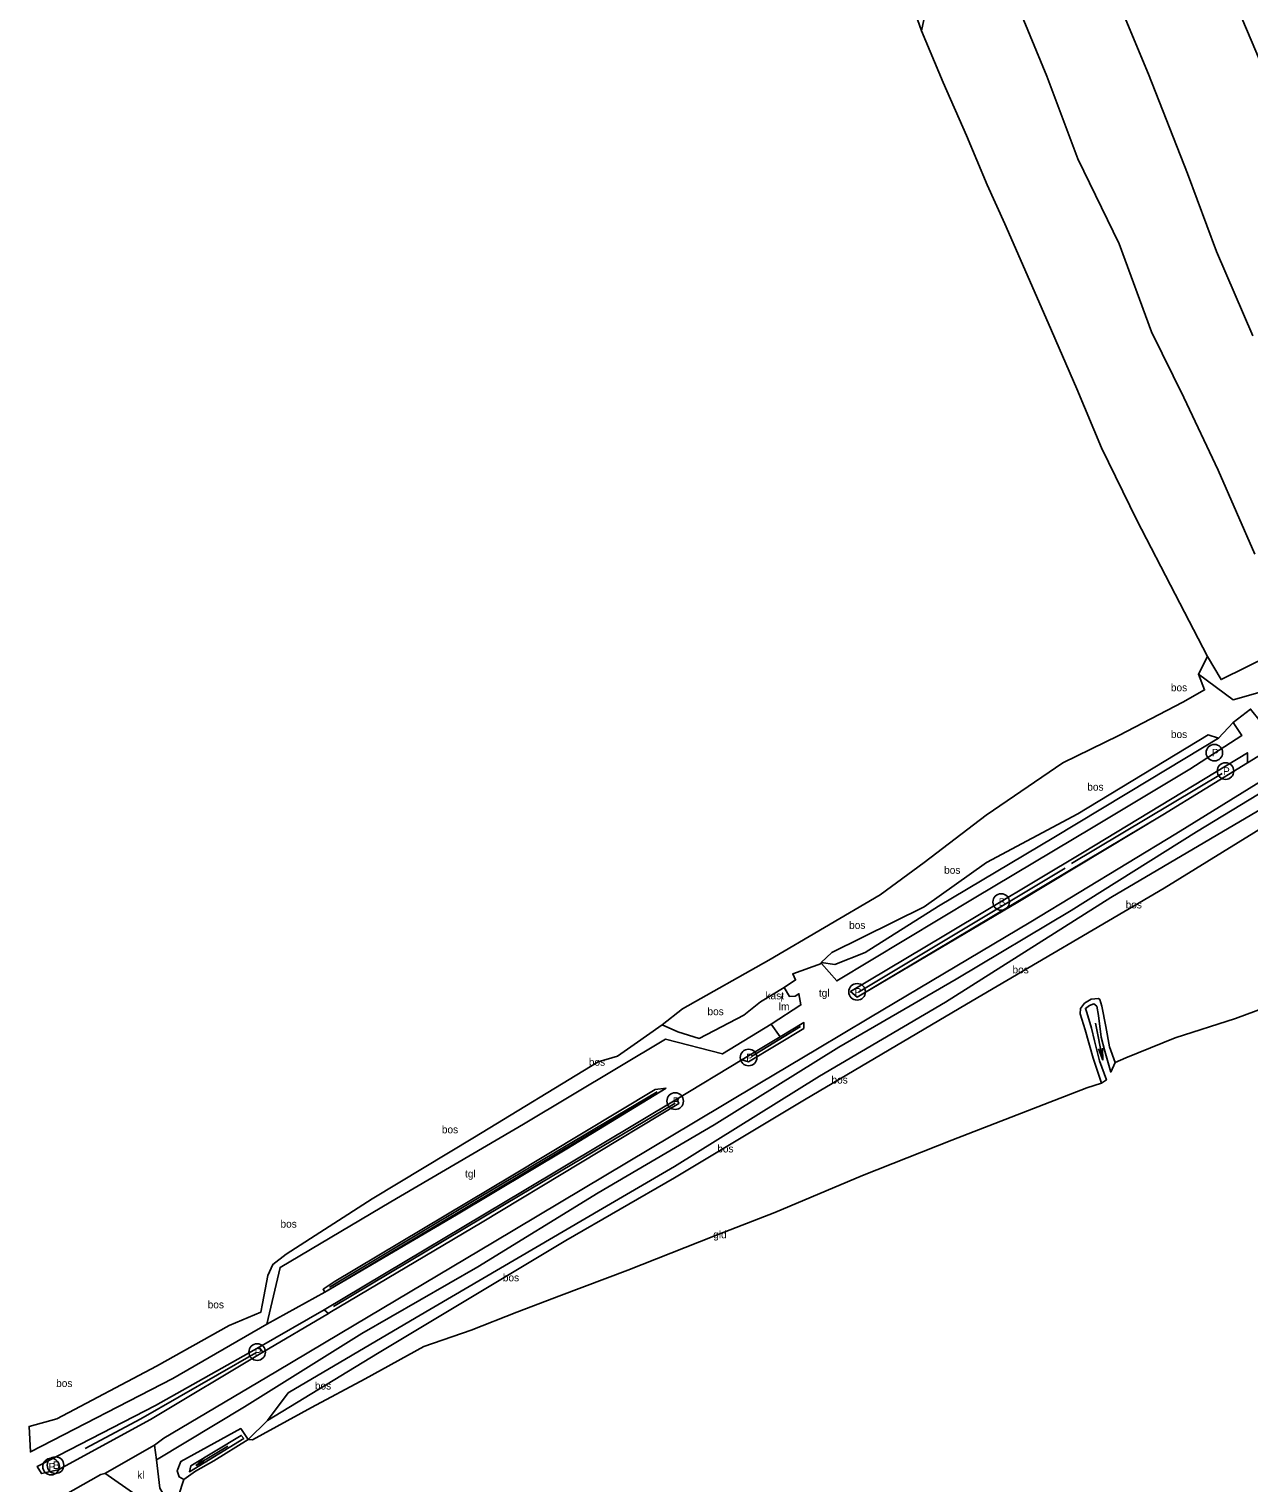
# Model space of a CAD drawing. Extents: x 154825 to 158680, y 370717 to 378075.
# Drawn here: x 156741.4 to 156903, y 374582.3 to 374775 of the extents above; entities that cross this region are included whole.
import ezdxf

# ---------------------------------------------------------------- set-up
doc = ezdxf.new("R2010")
doc.units = 0
for name, color, linetype in [('bos(vs)', 7, 'Continuous'), ('brandkraan', 7, 'Continuous'), ('cultuurscheiding', 7, 'Continuous'), ('grasland_productiegrasl(vs)', 7, 'Continuous'), ('haag geschoren', 7, 'Continuous'), ('hoogteverschillijn', 7, 'Continuous'), ('insteek sloot', 7, 'Continuous'), ('kast_huis(vs)', 7, 'Continuous'), ('klinkerverharding(vs)', 7, 'Continuous'), ('maaiveldlijn algemeen - gesloten verharding', 7, 'Continuous'), ('maaiveldlijn algemeen - onverhard', 7, 'Continuous'), ('maaiveldlijn algemeen - open verharding', 7, 'Continuous'), ('paal', 7, 'Continuous'), ('rioolput(z_inl)', 7, 'Continuous'), ('Sloot bodem', 7, 'Continuous'), ('stroomrichting  watergangen', 7, 'Continuous'), ('talud(boven)', 7, 'Continuous'), ('talud(onder)', 7, 'Continuous'), ('tegelverh(vs)', 7, 'Continuous'), ('verlichtingsobject', 7, 'Continuous'), ('vlak_Bos', 7, 'Continuous'), ('vlak_Grasland', 7, 'Continuous'), ('vlak_Grazige_vegetatie', 7, 'Continuous')]:
    doc.layers.add(name, color=color, linetype=linetype)

msp = doc.modelspace()

# ---------------------------------------------------------------- linework, layer by layer
at = {"layer": 'brandkraan'}
for centre in [(156870.19, 374659.33), (156744.87, 374584.69)]:
    msp.add_circle(centre, 1.1, dxfattribs=at)
at = {"layer": 'cultuurscheiding'}
for points in [[(156846.34, 374651.32), (156846.36, 374651.17)], [(156772.96, 374590.6), (156770.39, 374588.09)]]:
    msp.add_lwpolyline(points, dxfattribs=at)
at = {"layer": 'haag geschoren'}
for points in [[(156899.46, 374676.34), (156879.53, 374664.42)], [(156878.66, 374663.8), (156851.27, 374647.37)], [(156843.61, 374642.82), (156837.12, 374638.87)], [(156781.2, 374608.28), (156801.24, 374620.31), (156824.59, 374634.15)], [(156826.99, 374632.67), (156806.43, 374620.49), (156781.72, 374605.71)], [(156748.8, 374586.88), (156756.17, 374590.82), (156771.41, 374599.56)]]:
    msp.add_lwpolyline(points, dxfattribs=at)
at = {"layer": 'hoogteverschillijn'}
for points in [[(156906.89, 374765.1), (156900.83, 374779.42), (156895.29, 374790.91), (156892.3, 374798.62), (156888.93, 374809.37), (156883.22, 374823.42), (156878.09, 374833.76), (156873.64, 374844.16), (156870.51, 374852.35), (156885.33, 374851.51), (156889.19, 374839.09), (156893.87, 374827.16), (156900.6, 374813.06), (156904.67, 374802.28)], [(156861.71, 374784.61), (156859.64, 374774.79), (156862.52, 374767.96), (156865.59, 374760.91), (156868.35, 374754.39), (156870.67, 374749.2), (156876.43, 374736.08), (156880.22, 374727.34), (156883.49, 374719.54), (156888.18, 374709.95), (156893.24, 374700.14), (156897.54, 374691.85), (156899.34, 374688.81), (156909.11, 374693.65)], [(156903.82, 374705.44), (156898.94, 374716.58), (156894.39, 374726.19), (156890.13, 374734.89), (156885.83, 374746.54), (156880.35, 374757.82), (156876.25, 374768.8), (156868.98, 374786.36)], [(156885.16, 374779.99), (156889.73, 374769.04), (156894.9, 374755.89), (156898.74, 374745.56), (156903.52, 374734.35)], [(156897.14, 374687.45), (156894.28, 374685.82), (156885.77, 374681.4), (156878.35, 374677.79), (156868.18, 374670.84), (156859.97, 374664.58), (156854.17, 374660.28), (156839.39, 374651.63), (156827.98, 374645.17)]]:
    msp.add_lwpolyline(points, dxfattribs=at)
at = {"layer": 'insteek sloot'}
for points in [[(156885.28, 374638.08), (156884.55, 374640.13), (156884.08, 374642.85), (156883.53, 374645.53), (156883.26, 374646.4), (156883.07, 374646.53), (156882.12, 374646.46), (156881.23, 374645.92), (156880.7, 374645.2), (156880.65, 374644.53), (156881.31, 374642.37), (156882.38, 374638.63), (156883.49, 374635.32)], [(156760.99, 374583.95), (156761.47, 374585.18), (156769.43, 374589.54), (156770.39, 374588.09), (156765.84, 374585.28), (156763.41, 374583.88), (156761.9, 374582.77), (156761.28, 374583.14), (156760.99, 374583.95)]]:
    msp.add_lwpolyline(points, dxfattribs=at)
at = {"layer": 'maaiveldlijn algemeen - gesloten verharding'}
for points in [[(157058.6, 374771.83), (157053.73, 374771.53), (157045.22, 374769.71), (157038.94, 374767.46), (157031.29, 374763.24), (157011.53, 374750.26), (156995.5, 374739.35), (156979.43, 374728.54), (156960.29, 374715.43), (156941.93, 374703), (156924.07, 374691.06), (156908.52, 374681.28), (156902.82, 374677.77)], [(156851.1, 374646.72), (156872.4, 374659.33), (156891.62, 374670.88), (156902.82, 374677.77)], [(156904.56, 374675.28), (156893.34, 374668.37), (156874.12, 374656.72), (156852.66, 374643.95), (156845.85, 374639.86), (156838.19, 374635.32), (156829.41, 374630.05), (156803, 374614.29), (156782.6, 374602.13), (156774.06, 374597.07), (156759.21, 374588.25), (156757.98, 374587.36), (156751.4, 374583.6), (156750.89, 374583.46), (156744.87, 374580.05)], [(156833.25, 374639.19), (156839.7, 374643.15)], [(156836.72, 374638.13), (156844.05, 374642.55)], [(156840.89, 374641.46), (156835.82, 374638.42)], [(156827.19, 374633.18), (156835.82, 374638.42)], [(156741.54, 374586.44), (156760.43, 374596.16), (156772.88, 374603.37), (156780.58, 374607.64), (156798, 374617.87), (156812.63, 374626.63), (156825.78, 374634.65)], [(156827.19, 374633.18), (156806.98, 374621.08), (156780.48, 374605.27)], [(156781.05, 374604.81), (156781.24, 374604.92), (156801.43, 374616.91), (156827.47, 374632.62)], [(156780.48, 374605.27), (156771.88, 374600.33)], [(156771.88, 374600.33), (156758.12, 374592.6), (156742.44, 374584.5)], [(156743.03, 374583.57), (156745.22, 374584.07), (156757.45, 374590.74), (156772.33, 374599.68)]]:
    msp.add_lwpolyline(points, dxfattribs=at)
at = {"layer": 'maaiveldlijn algemeen - onverhard'}
msp.add_lwpolyline([(157058.79, 374767.5), (157053.23, 374767.29), (157044.62, 374765.16), (157036.01, 374761.41), (157026.76, 374755.54), (157007.61, 374742.48), (156990.57, 374730.49), (156972.05, 374718.4), (156957.88, 374708.78), (156939.57, 374696.45), (156923.4, 374685.78), (156904.31, 374673.64), (156896.07, 374668.65), (156879.45, 374658.2), (156864.22, 374649.12), (156848.69, 374640.08), (156832.16, 374629.8), (156816.8, 374620.8), (156800.84, 374610.97), (156785.45, 374602.16), (156769.9, 374592.43), (156758.26, 374585.38)], dxfattribs=at)
at = {"layer": 'maaiveldlijn algemeen - open verharding'}
for points in [[(156840.89, 374641.46), (156839.7, 374643.15), (156843.66, 374645.69), (156843.39, 374647.16), (156842.87, 374646.83), (156842.14, 374646.8), (156841.44, 374648.01), (156842.94, 374649.01), (156842.58, 374649.83), (156846.36, 374651.17), (156848.4, 374648.87), (156866.6, 374659.85), (156882.36, 374669.24), (156895.21, 374676.93), (156902.09, 374681.41), (156900.91, 374683.13), (156903.23, 374684.89), (156904.51, 374683.28), (156907.01, 374685.21), (156908.93, 374686.88)], [(156902.82, 374677.77), (156902.83, 374679.11), (156881.18, 374665.97), (156862.57, 374654.84), (156850.24, 374647.46), (156851.1, 374646.72)], [(156844.05, 374642.55), (156844.05, 374643.34), (156840.89, 374641.46)], [(156825.72, 374641.15), (156806.91, 374629.87), (156789.32, 374619.61), (156774.64, 374610.9), (156772.88, 374603.37)], [(156825.72, 374641.15), (156806.91, 374629.87), (156789.32, 374619.61), (156774.64, 374610.9), (156772.88, 374603.38)], [(156833.25, 374639.19), (156825.72, 374641.15)], [(156835.82, 374638.42), (156836.72, 374638.13)], [(156825.78, 374634.65), (156824.33, 374634.47), (156805.27, 374623.01), (156781.78, 374608.99), (156780.34, 374608.01), (156780.58, 374607.64)], [(156827.47, 374632.62), (156827.19, 374633.18)], [(156781.05, 374604.81), (156772.33, 374599.68), (156771.88, 374600.33)], [(156780.48, 374605.27), (156781.05, 374604.81)], [(156757.98, 374587.36), (156758.26, 374585.38), (156758.68, 374581.66), (156760.49, 374578.61), (156757.22, 374577.77), (156755.53, 374580.75), (156751.42, 374583.61)]]:
    msp.add_lwpolyline(points, dxfattribs=at)
at = {"layer": 'paal'}
for centre in [(156898.44, 374679.12), (156899.92, 374676.68), (156851.1, 374647.42), (156836.72, 374638.72), (156826.99, 374632.94), (156771.6, 374599.68), (156744.29, 374584.5)]:
    msp.add_circle(centre, 1.1, dxfattribs=at)
at = {"layer": 'Sloot bodem'}
for points in [[(156884.13, 374635.76), (156883.24, 374638.27), (156882.54, 374640.92), (156882.14, 374642.63), (156881.53, 374644.7), (156881.35, 374645.23), (156881.91, 374645.6), (156882.48, 374645.82), (156882.86, 374645.52), (156883.09, 374644.29), (156883.46, 374641.4), (156883.92, 374639.57), (156884.7, 374636.78)], [(156762.62, 374583.81), (156769.82, 374588.23), (156769.49, 374588.63), (156762.82, 374584.61), (156762.62, 374583.81)]]:
    msp.add_lwpolyline(points, dxfattribs=at)
at = {"layer": 'stroomrichting  watergangen'}
for p, q in [((156882.69, 374643.28), (156883.64, 374638.38)), ((156883.64, 374638.38), (156883.07, 374639.85)), ((156883.65, 374638.39), (156883.62, 374639.97)), ((156767.73, 374587.19), (156763.45, 374584.63)), ((156763.45, 374584.63), (156764.64, 374585.67)), ((156763.47, 374584.63), (156764.94, 374585.19))]:
    msp.add_line(p, q, dxfattribs=at)
at = {"layer": 'talud(boven)'}
for points in [[(156772.96, 374590.6), (156775.72, 374594.3), (156792.67, 374604.26), (156817.36, 374618.73), (156826.88, 374624.27), (156846.11, 374636.24), (156862.8, 374646.07), (156884.7, 374659.93), (156904.91, 374671.81), (156925.89, 374685.68), (156949.71, 374700.68), (156972.57, 374715.38), (156996.68, 374729.67), (157010.4, 374741.2), (157022.62, 374750.04), (157030.71, 374754.72), (157041.7, 374761.71), (157045.38, 374763.26), (157052.52, 374764.99), (157055.09, 374764.98), (157057.28, 374765.21), (157058.53, 374764.94), (157063.79, 374759.97), (157063.01, 374758.47)], [(156846.34, 374651.32), (156847.76, 374652.64), (156859.99, 374658.69), (156868.25, 374664.58), (156880.34, 374671.03), (156897.63, 374681.48), (156899, 374681.04)], [(156741.37, 374589.83), (156745.07, 374590.84), (156758.24, 374597.82), (156767.9, 374603.21), (156772.07, 374604.96), (156772.32, 374606.13), (156773.03, 374609.81), (156773.67, 374611.29), (156775.43, 374612.65), (156786.84, 374619.98), (156800.41, 374628.16), (156816.8, 374638.13), (156819.34, 374638.91), (156821.57, 374640.44), (156825.26, 374643.05), (156827.36, 374642.11), (156830.18, 374641.25), (156836.07, 374644.31), (156838.29, 374646.12), (156841.44, 374648.01)]]:
    msp.add_lwpolyline(points, dxfattribs=at)
at = {"layer": 'talud(onder)'}
for points in [[(157066.08, 374785.29), (157065.76, 374784.59), (157062.71, 374783.71), (157056.46, 374781.82), (157048.33, 374779.45), (157042.28, 374777.13), (157036.32, 374774.56), (157027.45, 374769.57), (157015.6, 374762.27), (156994.36, 374748.1), (156977.05, 374736.39), (156960.33, 374725.15), (156934.34, 374707.46), (156912.59, 374692.79), (156904.49, 374687.16), (156900.93, 374686.12), (156896.33, 374689.54)], [(156772.96, 374590.6), (156787.56, 374599.51), (156812.49, 374614.45), (156826.88, 374622.79), (156844.14, 374633.09), (156865.61, 374645.77), (156891.78, 374661.17), (156928.95, 374684.11), (156952.17, 374699.94), (156973.3, 374714.26), (156996.6, 374727.17), (157013.29, 374740.31), (157036.54, 374756.04), (157041.47, 374758.97), (157047.28, 374762.15), (157052.37, 374763.33), (157055.33, 374763.63), (157058.53, 374763.29), (157059.33, 374761.44), (157062.06, 374759.39), (157063.01, 374758.47)], [(156900.91, 374683.13), (156899, 374681.04), (156889.85, 374675.54), (156877.15, 374667.9), (156861.9, 374658.8), (156852.18, 374652.62), (156848.16, 374651.03), (156846.34, 374651.32)]]:
    msp.add_lwpolyline(points, dxfattribs=at)
at = {"layer": 'vlak_Bos'}
for points in [[(156903.23, 374684.89), (156900.91, 374683.13), (156899, 374681.04), (156897.63, 374681.48), (156880.34, 374671.03), (156868.25, 374664.58), (156859.99, 374658.69), (156847.76, 374652.64), (156846.34, 374651.32), (156846.36, 374651.17), (156842.58, 374649.83), (156842.94, 374649.01), (156841.44, 374648.01), (156838.29, 374646.12), (156836.07, 374644.31), (156830.18, 374641.25), (156827.36, 374642.11), (156825.26, 374643.05), (156827.98, 374645.17), (156839.39, 374651.63), (156854.17, 374660.28), (156859.97, 374664.58), (156868.18, 374670.84), (156878.35, 374677.79), (156885.77, 374681.4), (156894.28, 374685.82), (156897.14, 374687.45), (156896.33, 374689.54), (156900.93, 374686.12), (156904.49, 374687.16)], [(156928.95, 374684.11), (156891.78, 374661.17), (156865.61, 374645.77), (156844.14, 374633.09), (156826.88, 374622.79), (156812.49, 374614.45), (156787.56, 374599.51), (156772.96, 374590.6), (156775.72, 374594.3), (156792.67, 374604.26), (156817.36, 374618.73), (156826.88, 374624.27), (156846.11, 374636.24), (156862.8, 374646.07), (156884.7, 374659.93), (156904.91, 374671.81)]]:
    msp.add_lwpolyline(points, dxfattribs=at)
at = {"layer": 'vlak_Grasland'}
for points in [[(156904.49, 374687.16), (156900.93, 374686.12), (156896.33, 374689.54), (156897.54, 374691.85), (156893.24, 374700.14), (156888.18, 374709.95), (156883.49, 374719.54), (156880.22, 374727.34), (156876.43, 374736.08), (156870.67, 374749.2), (156868.35, 374754.39), (156865.59, 374760.91), (156862.52, 374767.96), (156859.64, 374774.79), (156858.33, 374778.4)], [(156909.47, 374646.92), (156901.26, 374643.91), (156893.25, 374641.32), (156886.7, 374638.66), (156885.28, 374638.08), (156884.55, 374640.13), (156884.08, 374642.85), (156883.53, 374645.53), (156883.26, 374646.4), (156883.07, 374646.53), (156882.12, 374646.46), (156881.23, 374645.92), (156880.7, 374645.2), (156880.65, 374644.53), (156881.31, 374642.37), (156882.38, 374638.63), (156883.49, 374635.32), (156881.53, 374634.68), (156863.64, 374627.75), (156851.83, 374623.08), (156840.18, 374618.2), (156832.1, 374615.02), (156820.7, 374610.53), (156811.91, 374607.22), (156806.02, 374604.96), (156799.94, 374602.58), (156793.7, 374600.41), (156785.93, 374596.13), (156778.78, 374592.34), (156770.98, 374588.05), (156770.39, 374588.09), (156772.96, 374590.6), (156787.56, 374599.51), (156812.49, 374614.45), (156826.88, 374622.79), (156844.14, 374633.09), (156865.61, 374645.77), (156891.78, 374661.17), (156928.95, 374684.11)]]:
    msp.add_lwpolyline(points, dxfattribs=at)
at = {"layer": 'vlak_Grazige_vegetatie'}
for points in [[(156866.6, 374659.85), (156848.4, 374648.87), (156846.36, 374651.17), (156846.34, 374651.32), (156848.16, 374651.03), (156852.18, 374652.62), (156861.9, 374658.8), (156877.15, 374667.9), (156889.85, 374675.54), (156899, 374681.04), (156900.91, 374683.13), (156902.09, 374681.41), (156895.21, 374676.93), (156882.36, 374669.24)], [(156852.18, 374652.62), (156848.16, 374651.03), (156846.34, 374651.32), (156847.76, 374652.64), (156859.99, 374658.69), (156868.25, 374664.58), (156880.34, 374671.03), (156897.63, 374681.48), (156899, 374681.04), (156889.85, 374675.54), (156877.15, 374667.9), (156861.9, 374658.8)], [(156891.62, 374670.88), (156851.1, 374646.72), (156850.24, 374647.46), (156862.57, 374654.84), (156881.18, 374665.97), (156902.83, 374679.11), (156902.82, 374677.77)], [(156841.44, 374648.01), (156842.14, 374646.8), (156842.87, 374646.83), (156843.39, 374647.16), (156843.66, 374645.69), (156839.7, 374643.15), (156833.25, 374639.19), (156825.72, 374641.15), (156806.91, 374629.87), (156789.32, 374619.61), (156774.64, 374610.9), (156772.88, 374603.37), (156760.43, 374596.16), (156741.54, 374586.44), (156741.37, 374589.83), (156745.07, 374590.84), (156758.24, 374597.82), (156767.9, 374603.21), (156772.07, 374604.96), (156772.32, 374606.13), (156773.03, 374609.81), (156773.67, 374611.29), (156775.43, 374612.65), (156786.84, 374619.98), (156800.41, 374628.16), (156816.8, 374638.13), (156819.34, 374638.91), (156821.57, 374640.44), (156825.26, 374643.05), (156827.36, 374642.11), (156830.18, 374641.25), (156836.07, 374644.31), (156838.29, 374646.12)], [(156883.26, 374646.4), (156883.53, 374645.53), (156884.08, 374642.85), (156884.55, 374640.13), (156885.28, 374638.08), (156884.7, 374636.78), (156883.92, 374639.57), (156883.46, 374641.4), (156883.09, 374644.29), (156882.86, 374645.52), (156882.48, 374645.82), (156881.91, 374645.6), (156881.35, 374645.23), (156881.53, 374644.7), (156882.14, 374642.63), (156882.54, 374640.92), (156883.24, 374638.27), (156884.13, 374635.76), (156883.49, 374635.32), (156882.38, 374638.63), (156881.31, 374642.37), (156880.65, 374644.53), (156880.7, 374645.2), (156881.23, 374645.92), (156882.12, 374646.46), (156883.07, 374646.53)], [(156844.05, 374642.55), (156836.72, 374638.13), (156835.82, 374638.42), (156840.89, 374641.46), (156844.05, 374643.34)], [(156825.78, 374634.65), (156780.58, 374607.64), (156780.34, 374608.01), (156781.78, 374608.99), (156805.27, 374623.01), (156824.33, 374634.47)], [(156781.24, 374604.92), (156781.05, 374604.81), (156780.48, 374605.27), (156806.98, 374621.08), (156827.19, 374633.18), (156827.47, 374632.62), (156801.43, 374616.91)], [(156745.22, 374584.07), (156743.03, 374583.57), (156742.44, 374584.5), (156758.12, 374592.6), (156771.88, 374600.33), (156772.33, 374599.68), (156757.45, 374590.74)], [(156769.43, 374589.54), (156770.39, 374588.09), (156765.84, 374585.28), (156763.41, 374583.88), (156761.9, 374582.77), (156761.28, 374583.14), (156760.99, 374583.95), (156761.47, 374585.18)], [(156762.82, 374584.61), (156762.62, 374583.81), (156769.82, 374588.23), (156769.49, 374588.63)]]:
    msp.add_lwpolyline(points, close=True, dxfattribs=at)
for points in [[(156758.68, 374581.66), (156758.26, 374585.38), (156769.9, 374592.43), (156785.45, 374602.16), (156800.84, 374610.97), (156816.8, 374620.8), (156832.16, 374629.8), (156848.69, 374640.08), (156864.22, 374649.12), (156879.45, 374658.2), (156896.07, 374668.65), (156904.31, 374673.64)], [(156904.91, 374671.81), (156884.7, 374659.93), (156862.8, 374646.07), (156846.11, 374636.24), (156826.88, 374624.27), (156817.36, 374618.73), (156792.67, 374604.26), (156775.72, 374594.3), (156772.96, 374590.6), (156770.39, 374588.09), (156769.43, 374589.54), (156761.47, 374585.18), (156760.99, 374583.95), (156761.28, 374583.14), (156761.9, 374582.77), (156760.49, 374578.61)]]:
    msp.add_lwpolyline(points, dxfattribs=at)

# ---------------------------------------------------------------- texts
at = {"layer": 'bos(vs)'}
for p in [(156892.68, 374687.26), (156892.68, 374681.06), (156881.6, 374674.09), (156862.63, 374663.07), (156886.68, 374658.48), (156850.04, 374655.77), (156871.69, 374649.87), (156831.27, 374644.33), (156815.55, 374637.63), (156847.7, 374635.27), (156796.07, 374628.68), (156832.57, 374626.14), (156774.69, 374616.17), (156804.15, 374609.06), (156765.04, 374605.48), (156744.96, 374595.05), (156779.25, 374594.72)]:
    msp.add_text('bos', height=1, dxfattribs=at).set_placement(p)
at = {"layer": 'brandkraan'}
for p in [(156869.86, 374658.83), (156744.54, 374584.19)]:
    msp.add_text('B', height=1, dxfattribs=at).set_placement(p)
at = {"layer": 'grasland_productiegrasl(vs)'}
msp.add_text('gld', height=1, dxfattribs=at).set_placement((156832.03, 374614.76))
at = {"layer": 'kast_huis(vs)'}
msp.add_text('kast', height=1, dxfattribs=at).set_placement((156838.96, 374646.43))
at = {"layer": 'klinkerverharding(vs)'}
msp.add_text('kl', height=1, dxfattribs=at).set_placement((156755.7, 374582.89))
at = {"layer": 'paal'}
for p in [(156898.11, 374678.62), (156899.59, 374676.18), (156850.77, 374646.92), (156836.39, 374638.22), (156826.66, 374632.44), (156771.27, 374599.18), (156743.96, 374584)]:
    msp.add_text('P', height=1, dxfattribs=at).set_placement(p)
at = {"layer": 'rioolput(z_inl)'}
msp.add_text('r', height=1, dxfattribs=at).set_placement((156840.9, 374646.14))
at = {"layer": 'tegelverh(vs)'}
for p in [(156846.03, 374646.78), (156799.14, 374622.82)]:
    msp.add_text('tgl', height=1, dxfattribs=at).set_placement(p)
at = {"layer": 'verlichtingsobject'}
msp.add_text('lm', height=1, dxfattribs=at).set_placement((156840.72, 374644.98))

doc.saveas('drawing.dxf')
